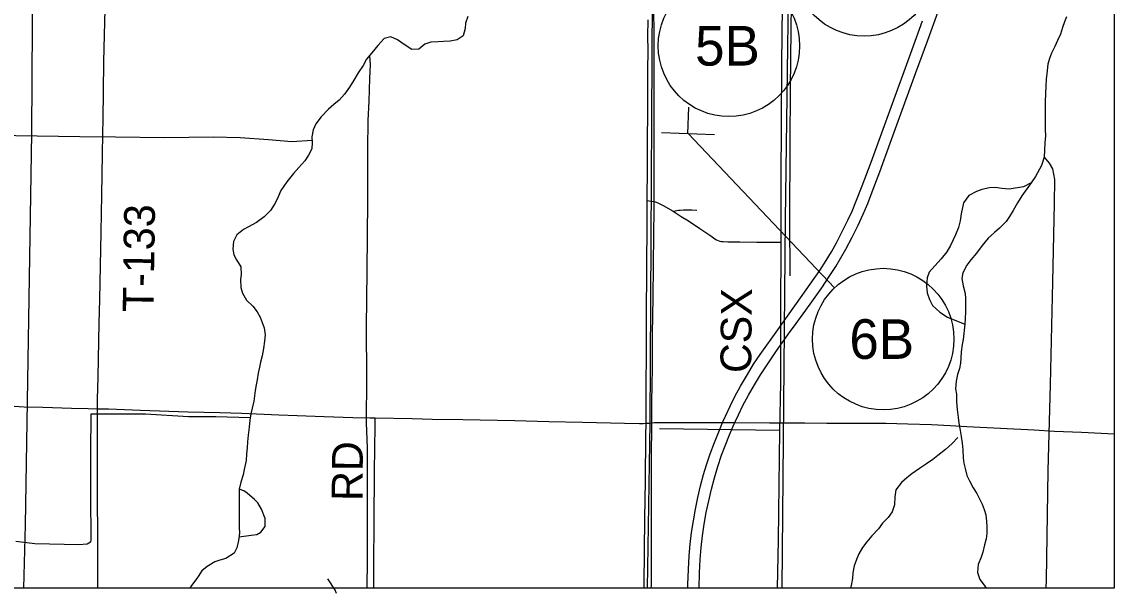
# Model space of a CAD drawing. Extents: x 0 to 680, y 0 to 834.
# Drawn here: x 297.4 to 374.7, y 63.7 to 104.1 of the extents above; entities that cross this region are included whole.
import ezdxf

# ---------------------------------------------------------------- set-up
doc = ezdxf.new("R2010")
doc.units = 0
for name, color, linetype in [('GM_X_Interstate_Route', 7, 'Continuous'), ('GM_X_Minor_River', 7, 'Continuous'), ('GM_X_Rail_Line', 7, 'Continuous'), ('GM_X_Rail_Line_Text', 7, 'Continuous'), ('GM_X_State_Route', 7, 'Continuous'), ('GM_X_Township_Road', 7, 'Continuous'), ('GM_X_Township_Road_Text', 7, 'Continuous'), ('SH_Text', 7, 'Continuous')]:
    doc.layers.add(name, color=color, linetype=linetype)

msp = doc.modelspace()

# ---------------------------------------------------------------- linework, layer by layer
at = {"layer": 'GM_X_Interstate_Route'}
msp.add_lwpolyline([(44.693, 394.069), (374.693, 394.069), (374.693, 64.069), (44.693, 64.069)], close=True, dxfattribs=at)
for points in [[(345.345, 64.069), (345.375, 65.137), (345.426, 66.092), (345.497, 66.925), (345.591, 67.756), (345.709, 68.585), (345.852, 69.409), (346.021, 70.228), (346.215, 71.042), (346.433, 71.85), (346.673, 72.651), (346.937, 73.445), (347.182, 74.118), (347.491, 74.896), (347.821, 75.664), (347.862, 75.752), (348.123, 76.314), (348.444, 76.956), (348.839, 77.693), (349.254, 78.419), (349.691, 79.132), (350.147, 79.833), (350.822, 80.819), (351.786, 82.184), (352.016, 82.5), (353.187, 84.117), (354.015, 85.285), (354.549, 86.076), (355, 86.778), (355.369, 87.39), (355.721, 88.013), (356.165, 88.856), (356.588, 89.711), (356.936, 90.469), (357.263, 91.237), (357.655, 92.235), (358.116, 93.464), (358.851, 95.483), (360.649, 100.418), (361.509, 102.772), (362.246, 104.79)], [(344.548, 64.069), (344.551, 64.315), (344.585, 65.388), (344.641, 66.34), (344.716, 67.171), (344.815, 68), (344.937, 68.826), (345.082, 69.647), (345.251, 70.465), (345.442, 71.277), (345.66, 72.082), (345.867, 72.767), (346.134, 73.558), (346.421, 74.341), (346.777, 75.226), (347.005, 75.755), (347.201, 76.211), (347.554, 76.967), (347.877, 77.605), (348.276, 78.338), (348.757, 79.162), (349.197, 79.87), (349.661, 80.564), (350.906, 82.315), (351.996, 83.837), (352.226, 84.158), (353.19, 85.524), (353.869, 86.507), (354.324, 87.208), (354.696, 87.822), (355.048, 88.447), (355.493, 89.292), (355.862, 90.043), (356.16, 90.695), (356.484, 91.466), (356.876, 92.467), (357.499, 94.146), (358.736, 97.506), (360.405, 102.107), (361.146, 104.124)]]:
    msp.add_lwpolyline(points, dxfattribs=at)
at = {"layer": 'GM_X_Minor_River'}
for points in [[(351.702, 152.087), (351.629, 147.405), (351.52, 135.385), (351.483, 128.033), (351.356, 119.966), (351.26, 111.987), (351.21, 105.174), (351.169, 101.104), (351.114, 92.789), (351.127, 87.435), (351.104, 84.488), (351.101, 78.551), (351.032, 75.196), (350.922, 67.479), (350.857, 64.069)], [(352.398, 150.962), (352.346, 148.366), (352.318, 143.917), (352.278, 140.255), (352.237, 136.39), (352.122, 132.276), (352.142, 129.14), (352.046, 126.252), (352.004, 122.065), (352.003, 117.047), (351.907, 114.173), (351.898, 111.153), (351.871, 107.113), (351.831, 103.524), (351.79, 99.337), (351.749, 95.457), (351.733, 90.074), (351.75, 86.12)], [(328.99, 104.451), (328.828, 103.97), (328.798, 103.591), (328.665, 103.081), (328.227, 102.79), (327.746, 102.689), (327.265, 102.662), (326.886, 102.648), (326.376, 102.62), (325.953, 102.476), (325.53, 102.142), (325.034, 102.114), (324.482, 102.451), (324.002, 102.802), (323.536, 102.993), (323.07, 102.878), (322.631, 102.383), (322.207, 101.874), (321.827, 101.423), (321.578, 100.986), (321.227, 100.462), (320.919, 99.952), (320.626, 99.457), (320.261, 98.962), (319.895, 98.525), (319.501, 98.22), (319.136, 97.9), (318.624, 97.362), (318.244, 96.867), (318.039, 96.43), (317.95, 95.949), (317.978, 95.54), (317.947, 95.088), (317.713, 94.637), (317.464, 94.244), (317.04, 93.778), (316.66, 93.341), (316.192, 92.759), (315.768, 92.148), (315.577, 91.711), (315.371, 91.244), (315.035, 90.735), (314.596, 90.284), (314.042, 89.892), (313.487, 89.587), (313.122, 89.384), (312.655, 89.02), (312.406, 88.554), (312.36, 88), (312.447, 87.606), (312.635, 87.241), (312.94, 86.758), (312.952, 86.218), (312.922, 85.854), (312.935, 85.299), (313.05, 84.891), (313.34, 84.394), (313.791, 83.984), (314.081, 83.589), (314.298, 83.209), (314.587, 82.45), (314.644, 81.954), (314.599, 81.516), (314.539, 80.991), (314.45, 80.481), (314.333, 80.029), (314.244, 79.665), (314.17, 79.256), (314.081, 78.775)], [(371.313, 104.416), (371.181, 104.051), (371.049, 103.658), (370.902, 103.191), (370.696, 102.754), (370.491, 102.332), (370.257, 101.851), (370.124, 101.472), (370.007, 101.064), (369.932, 100.393), (369.887, 100.029), (369.856, 99.518), (369.84, 98.978), (369.824, 98.424), (369.808, 98.03), (369.807, 97.534), (369.82, 97.009), (369.818, 96.469), (369.831, 96.002), (369.786, 95.521), (369.77, 94.996), (369.739, 94.515), (369.544, 93.915), (369.416, 93.655), (369.123, 93.145), (368.83, 92.694), (368.157, 91.762), (367.864, 91.267), (367.542, 90.728), (367.293, 90.32), (367.059, 89.956), (366.592, 89.491), (366.227, 89.186), (365.774, 88.778), (365.35, 88.254), (364.969, 87.73), (364.56, 87.25), (364.267, 86.872), (364.003, 86.333), (363.929, 85.939), (364.015, 85.414), (364.159, 84.873), (364.187, 84.509), (364.185, 83.604), (364.154, 83.094), (364.124, 82.714), (364.004, 81.635), (363.944, 81.271), (363.885, 80.746)], [(322.027, 101.66), (322.088, 101.043), (322.027, 100.051), (321.978, 98.461), (321.916, 97.104), (321.895, 95.062), (321.899, 91.43), (321.84, 86.484), (321.799, 82.502), (321.818, 78.928), (321.794, 75.747), (321.861, 73.982), (321.879, 70.087), (321.867, 66.06), (321.843, 64.069)], [(317.968, 95.676), (316.535, 95.588), (314.89, 95.724), (312.894, 95.862), (310.986, 95.926), (307.547, 95.877), (304.08, 95.917), (301.56, 95.939), (297.014, 96.011), (292.12, 96.084), (287.881, 96.257), (283.263, 96.431)], [(369.739, 94.515), (370.088, 94.076), (370.334, 93.681), (370.463, 92.922), (370.458, 91.23), (370.339, 85.702), (370.157, 78.452), (369.993, 72.354), (369.883, 64.652), (369.863, 64.069)], [(368.83, 92.694), (368.284, 92.401), (367.27, 92.246), (366.76, 92.291), (366.28, 92.366), (365.886, 92.338), (365.347, 92.208), (364.953, 92.078), (364.428, 91.788), (364.033, 91.278), (363.885, 90.491), (363.796, 89.995), (363.692, 89.543), (363.472, 89.019), (363.311, 88.654), (363.12, 88.261), (362.871, 87.809), (362.462, 87.315), (362.023, 86.834), (361.6, 86.369), (361.467, 85.99), (361.422, 85.421), (361.479, 84.925), (361.638, 84.458), (361.855, 84.019), (362.363, 83.551), (362.901, 83.199), (364.124, 82.714)], [(363.885, 80.746), (363.854, 80.308), (363.824, 79.944), (363.75, 79.579), (363.618, 79.142), (363.514, 78.69), (363.483, 78.136), (363.541, 77.771), (363.553, 77.216), (363.581, 76.677), (363.667, 76.107), (363.709, 75.713), (363.781, 75.334)], [(314.081, 78.775), (314.022, 78.41), (313.948, 78.017), (313.903, 77.638), (313.843, 77.259), (313.74, 76.763), (313.651, 76.384), (313.577, 75.932), (313.517, 75.436), (313.443, 74.867), (313.412, 74.386), (313.382, 73.963), (313.337, 73.54), (313.306, 73.073), (313.159, 72.446), (313.099, 72.067), (312.938, 71.557), (312.82, 71.061), (312.815, 69.369), (312.828, 68.859), (312.826, 68.348), (312.839, 67.954), (312.78, 67.429), (312.647, 66.904), (312.471, 66.526), (311.872, 66.148), (311.45, 66.033), (311.085, 65.917), (310.56, 65.583), (310.18, 65.278), (309.814, 64.739), (309.448, 64.244), (309.336, 64.069)], [(313.602, 76.084), (311.174, 76.158), (309.222, 76.163), (306.192, 76.347), (302.331, 76.359), (302.309, 73.616), (302.299, 70.596), (302.334, 67.489), (302.304, 67.299), (302.071, 67.169), (301.488, 67.127), (298.37, 67.194), (297.03, 67.359)], [(351.032, 75.196), (342.539, 75.308)], [(363.781, 75.334), (363.867, 74.765), (363.938, 74.312), (363.995, 73.831), (364.023, 73.262), (364.065, 72.897), (364.151, 72.517), (364.266, 72.021), (364.469, 71.641), (364.73, 71.144), (364.976, 70.75), (365.179, 70.37), (365.353, 69.99), (365.512, 69.61), (365.613, 69.231), (365.655, 68.793), (365.683, 68.384), (365.682, 67.917), (365.637, 67.553), (365.534, 67.116), (365.401, 66.605), (365.283, 66.241), (365.078, 65.731), (365.018, 65.177), (365.191, 64.666), (365.496, 64.271), (365.633, 64.069)], [(363.633, 74.707), (363.239, 74.285), (362.757, 73.849), (362.231, 73.427), (361.866, 73.151), (361.413, 72.831), (360.932, 72.512), (360.391, 72.134), (360.026, 71.844), (359.661, 71.524), (359.252, 71.014), (359.177, 70.504), (359.161, 69.95), (358.999, 69.454), (358.707, 69.061), (358.312, 68.639), (358.034, 68.261), (357.566, 67.751), (357.215, 67.329), (356.908, 66.922), (356.645, 66.485), (356.483, 66.091), (356.307, 65.625), (356.218, 65.144), (356.188, 64.75), (356.114, 64.356), (356.054, 64.069)], [(312.809, 67.683), (313.655, 67.791), (314.063, 67.848), (314.355, 68.008), (314.647, 68.416), (314.649, 68.985), (314.403, 69.642), (314.143, 70.095), (313.91, 70.329), (313.387, 70.768), (313.143, 70.934), (312.82, 71.061)], [(319.062, 64.729), (319.609, 63.895), (319.673, 63.709)]]:
    msp.add_lwpolyline(points, dxfattribs=at)
at = {"layer": 'GM_X_Rail_Line'}
for points in [[(351.218, 64.069), (351.448, 90.121), (351.798, 116.184), (351.86, 139.423), (352.175, 154.252), (352.451, 189.912), (352.901, 229.863), (353.003, 247.107), (353.355, 298.069), (353.602, 311.675), (353.78, 316.856), (353.954, 319.076), (354.473, 323.516), (355.976, 338.772), (356.265, 341.847), (356.561, 344.985), (356.644, 347.076), (356.685, 349.146), (356.788, 357.395), (356.901, 372.817), (357.146, 391.252), (357.174, 394.069)], [(341.694, 64.069), (341.887, 75.733), (342.297, 152.995), (342.913, 209.384), (343.255, 230.188), (343.597, 251.334), (344.253, 291.298), (344.078, 319.736), (344.92, 358.256)], [(324.019, 224.102), (323.747, 191.887), (316.336, 170.579), (315.011, 167.69), (314.008, 166.083), (312.961, 164.64), (304.58, 156.45), (302.834, 154.704), (301.197, 152.565), (299.926, 150.355), (299.392, 148.48), (299.125, 146.806), (298.837, 143.215), (298.255, 115.425), (298.139, 96.174), (297.69, 68.538), (297.562, 64.069)]]:
    msp.add_lwpolyline(points, dxfattribs=at)
at = {"layer": 'GM_X_State_Route'}
for points in [[(341.962, 64.069), (341.964, 64.271), (341.973, 67.972), (341.983, 69.643), (341.985, 73.225), (341.996, 75.738), (342.003, 77.164), (342.015, 78.478), (342.035, 79.551), (342.035, 80.386), (342.057, 82.057), (342.091, 84.564), (342.143, 89.099), (342.154, 90.771), (342.164, 91.361), (342.17, 91.486), (342.173, 96.26), (342.17, 101.274), (342.174, 103.184), (342.15, 104.975)], [(341.454, 64.069), (341.457, 64.345), (341.514, 69), (341.543, 71.626), (341.585, 74.848), (341.59, 75.705), (341.603, 77.951), (341.611, 81.055), (341.617, 81.89), (341.633, 83.322), (341.671, 89.887), (341.676, 91.435), (341.683, 93.825), (341.701, 95.615), (341.707, 97.764), (341.716, 98.957), (341.722, 100.628), (341.736, 102.06), (341.721, 103.016), (341.74, 104.208)]]:
    msp.add_lwpolyline(points, dxfattribs=at)
at = {"layer": 'GM_X_Township_Road'}
for p, q in [((341.59, 75.705), (341.802, 75.72)), ((341.802, 75.72), (341.996, 75.738))]:
    msp.add_line(p, q, dxfattribs=at)
for points in [[(302.797, 76.737), (302.804, 77.403), (302.84, 78.954), (302.87, 80.266), (302.919, 82.773), (302.955, 84.443), (303, 86.83), (303.048, 89.217), (303.101, 91.842), (303.145, 94.707), (303.18, 96.138), (303.19, 97.212), (303.217, 99.122), (303.253, 101.271), (303.356, 105.925), (303.389, 106.998), (303.422, 108.43), (303.467, 110.577), (303.498, 112.008), (303.526, 113.201), (303.554, 114.514), (303.559, 115.188)], [(341.676, 91.435), (341.805, 91.418), (341.923, 91.403)], [(341.923, 91.403), (341.988, 91.394), (342.164, 91.361)], [(342.164, 91.361), (342.296, 91.321), (342.415, 91.278), (342.519, 91.235), (342.798, 91.092), (343.518, 90.683)], [(343.518, 90.683), (343.656, 90.713), (343.77, 90.734), (343.888, 90.751), (344.006, 90.763), (344.241, 90.779), (344.473, 90.788), (344.825, 90.783), (345.19, 90.77)], [(343.518, 90.683), (344.077, 90.322), (344.587, 89.995), (345.392, 89.474), (346.166, 88.936), (346.454, 88.741), (346.577, 88.662), (346.696, 88.609), (346.808, 88.576), (346.924, 88.556), (347.043, 88.543), (347.365, 88.527), (348.225, 88.514), (349.414, 88.505), (350.008, 88.499), (350.483, 88.497), (350.839, 88.488), (351.079, 88.49)], [(264.226, 77.903), (264.686, 77.885), (267.908, 77.789), (269.22, 77.759), (272.68, 77.661), (276.737, 77.567), (278.884, 77.497), (281.27, 77.446), (283.06, 77.407), (286.401, 77.306), (287.951, 77.247), (289.86, 77.196), (291.291, 77.134), (293.557, 77.06), (295.346, 76.989), (296.896, 76.91), (297.611, 76.877), (298.924, 76.845), (300.951, 76.771), (302.144, 76.743), (302.797, 76.737)], [(302.822, 64.069), (302.824, 66.302), (302.814, 68.57), (302.807, 69.644), (302.802, 71.435), (302.798, 73.463), (302.79, 76.089), (302.797, 76.737)], [(302.797, 76.737), (302.86, 76.737), (303.575, 76.716), (305.841, 76.623), (309.181, 76.518), (311.448, 76.46), (312.999, 76.422), (315.62, 76.303), (316.929, 76.259), (318.837, 76.187), (320.865, 76.123), (322.058, 76.091), (322.437, 76.084)], [(322.342, 64.069), (322.346, 65.536), (322.368, 68.878), (322.389, 72.102), (322.415, 74.131), (322.43, 75.324), (322.44, 75.802), (322.439, 75.921), (322.437, 76.084)], [(322.437, 76.084), (325.042, 76.036), (326.473, 75.996), (328.622, 75.965), (332.321, 75.893), (334.708, 75.837), (337.094, 75.79), (340.076, 75.715), (341.132, 75.684), (341.243, 75.683), (341.38, 75.691), (341.59, 75.705)], [(341.996, 75.738), (342.171, 75.754), (342.286, 75.762), (342.434, 75.769), (343.4, 75.767), (344.833, 75.763), (346.504, 75.757), (347.005, 75.755), (347.862, 75.752), (350.317, 75.745), (351.152, 75.737), (351.629, 75.734), (352.823, 75.73), (354.375, 75.72), (355.927, 75.717), (358.553, 75.704), (360.105, 75.675), (361.775, 75.612), (363.087, 75.547), (364.279, 75.484), (369.047, 75.235), (370.478, 75.158), (372.386, 75.067), (374.693, 74.95)]]:
    msp.add_lwpolyline(points, dxfattribs=at)
at = {"layer": 'SH_Text'}
for p, q in [((344.552, 96.162), (344.624, 98.036)), ((346.427, 96.09), (342.678, 96.233)), ((344.56, 96.176), (354.918, 85.277))]:
    msp.add_line(p, q, dxfattribs=at)
for centre in [(357.009, 108.052), (347.452, 102.372), (358.363, 81.653)]:
    msp.add_circle(centre, 5, dxfattribs=at)

# ---------------------------------------------------------------- texts
at = {"layer": 'GM_X_Rail_Line_Text'}
msp.add_text('CSX', height=2.1745, rotation=89.46978, dxfattribs=at).set_placement((349.019, 79.25))
at = {"layer": 'GM_X_Township_Road_Text'}
for s, rotation, p in [('T-133', 89.15818, (306.759, 83.541)), ('RD', 89.50635, (321.539, 70.212))]:
    msp.add_text(s, height=2.1818, rotation=rotation, dxfattribs=at).set_placement(p)
at = {"layer": 'SH_Text'}
for s, p in [('5B', (345.058, 100.972)), ('6B', (355.968, 80.253))]:
    msp.add_text(s, height=2.8, dxfattribs=at).set_placement(p)

doc.saveas('drawing.dxf')
